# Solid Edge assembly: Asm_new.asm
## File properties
Author: CADSoft
Template: Sync Iso Assembly.asm
Last saved by: Sarvanan
Revision: 9
Application: Solid Edge
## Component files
casting_new.par
brass_new.par
cap_1224.par
Bolt.par
Lock Nut.par
Nut.par
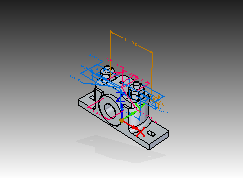
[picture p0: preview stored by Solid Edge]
